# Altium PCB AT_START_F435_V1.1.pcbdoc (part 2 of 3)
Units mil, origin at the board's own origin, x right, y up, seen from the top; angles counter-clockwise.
Board outline 6521.81 x 4041.5 mil, 2 copper layers (Top Layer, Bottom Layer); 158 components, 212 nets, 714 pads, 868 vias.
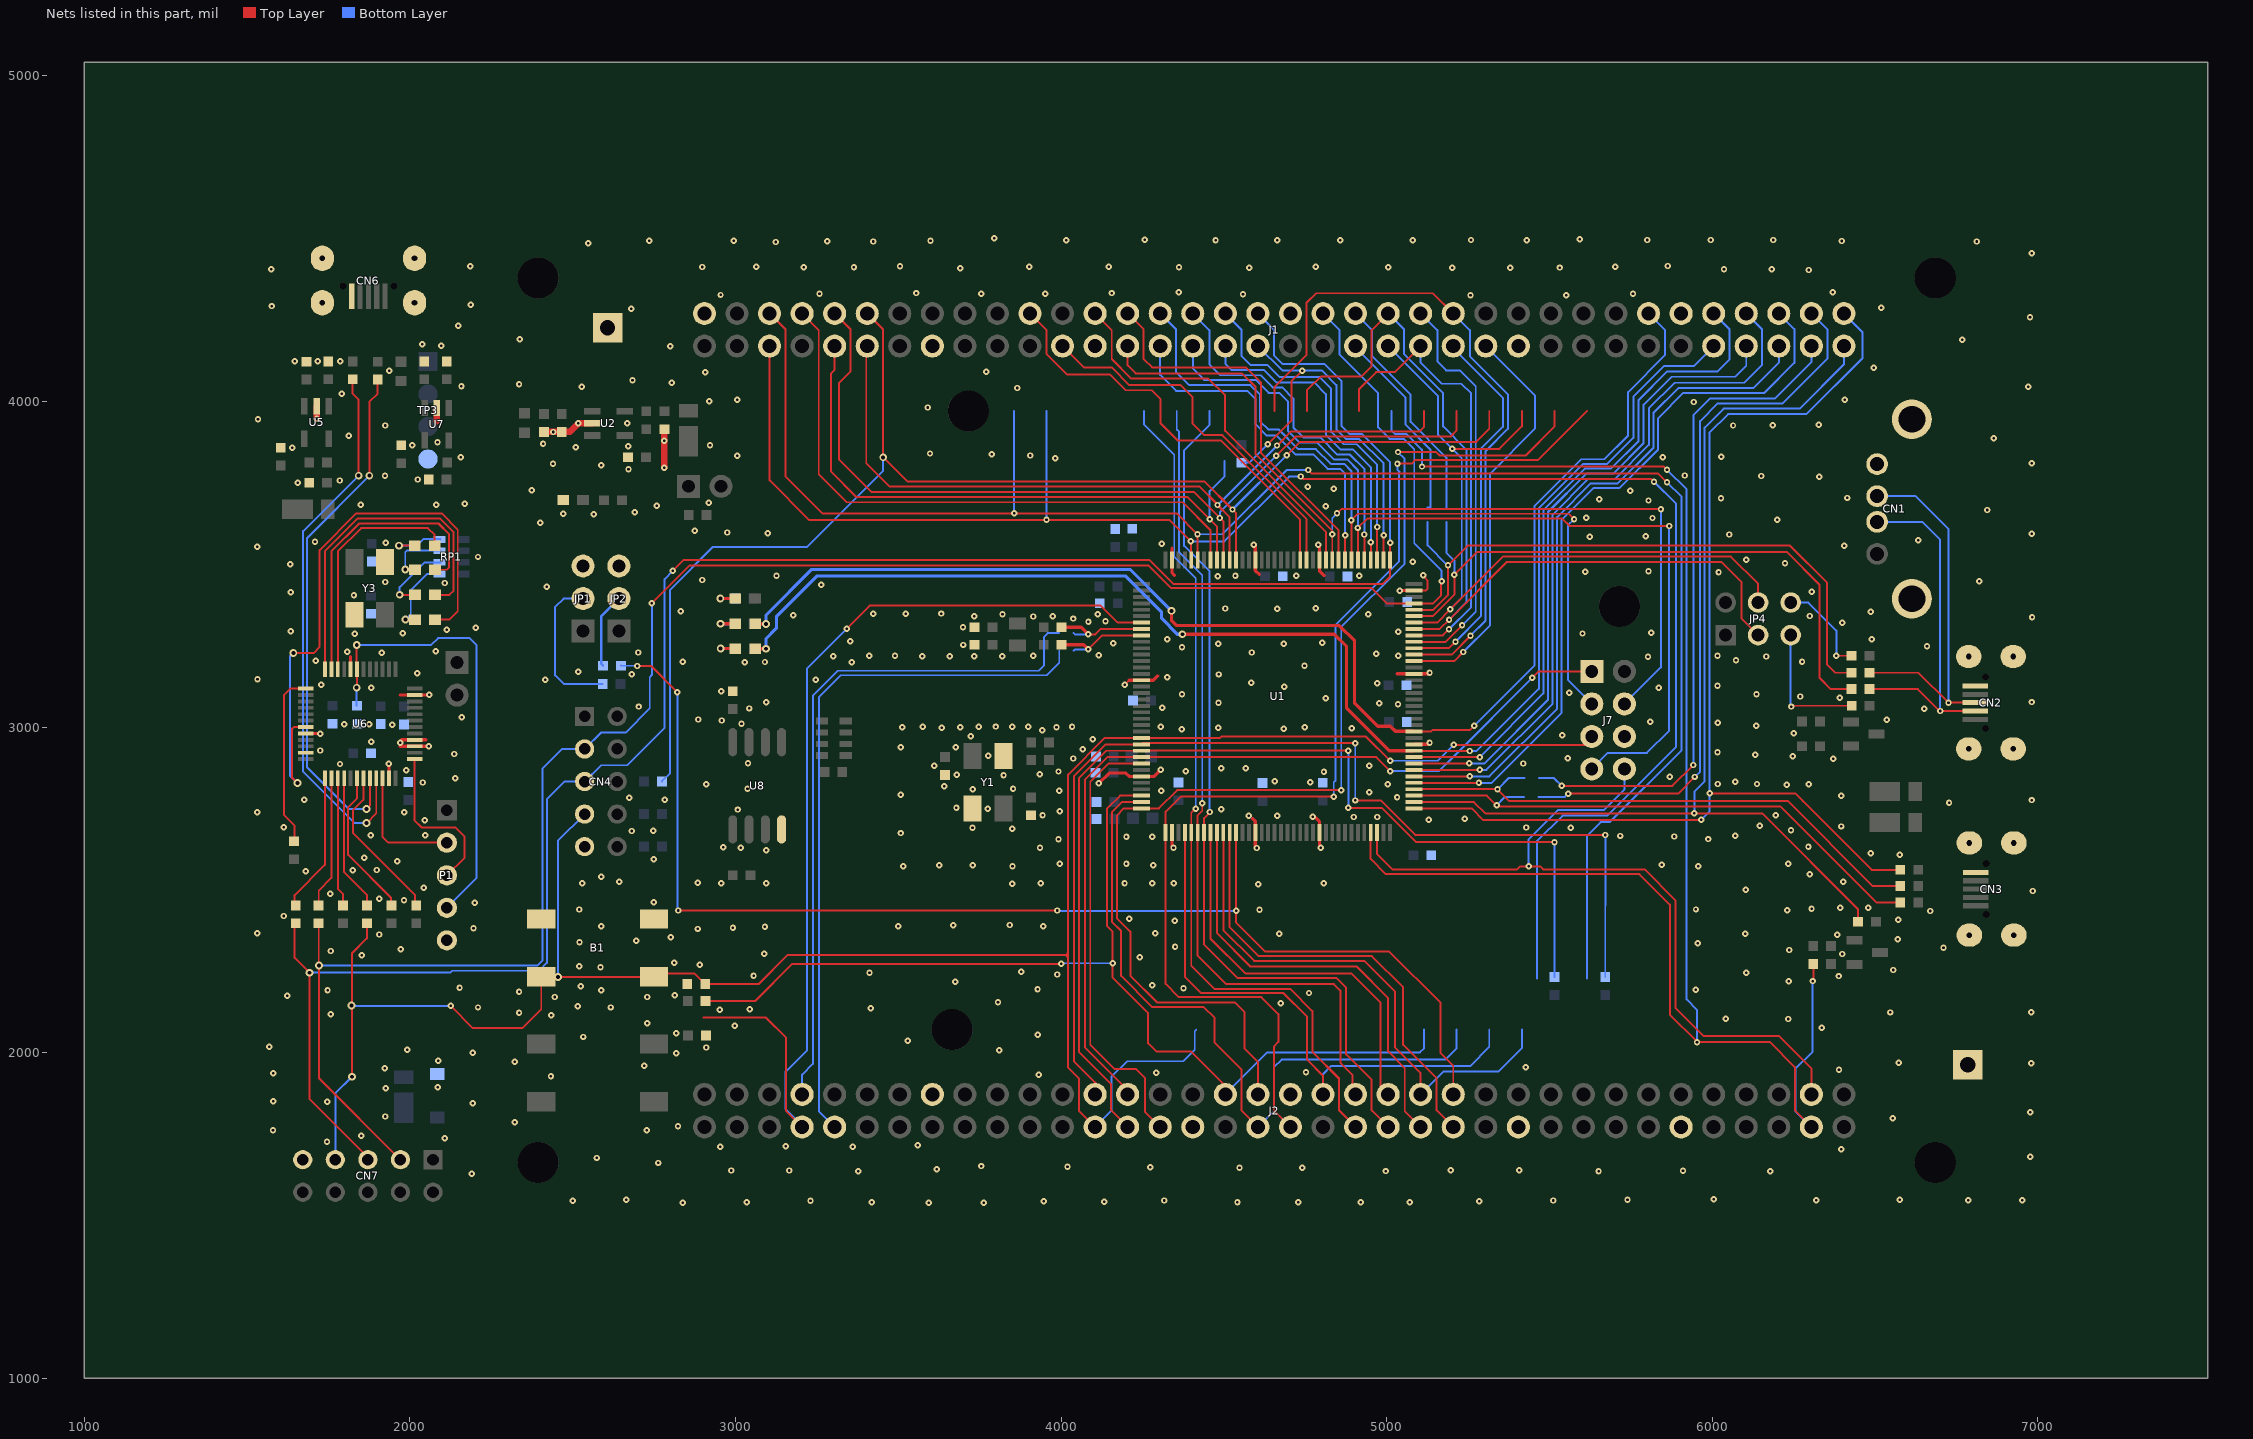
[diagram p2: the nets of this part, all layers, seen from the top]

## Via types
v1: diameter 19.69, hole 7.87, Top Layer to Bottom Layer, tented both sides, 787 vias
v2: diameter 23.62, hole 11.81, Top Layer to Bottom Layer, tented both sides, 53 vias
v3: diameter 24, hole 12, Top Layer to Bottom Layer, tented both sides, 17 vias
v4: diameter 35.43, hole 19.69, Top Layer to Bottom Layer, tented both sides, 11 vias

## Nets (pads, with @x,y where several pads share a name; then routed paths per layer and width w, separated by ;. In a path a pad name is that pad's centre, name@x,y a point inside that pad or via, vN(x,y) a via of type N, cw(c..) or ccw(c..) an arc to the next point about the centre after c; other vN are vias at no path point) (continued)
GND: B1.2 B1.4 C1.1 C2.1 C3.1 C4.1 C5.2 C6.2 C7.2 C8.2 C9.2 C10.2 C11.2 C12.2 C13.2 C14.2 C15.2 C16.2 C17.2 C18.2 C19.2 C20.2 C21.1 C22.2 C23.2 C24.2 C25.2 C26.2 C27.2 C28.2 C29.2 C30.2 C31.2 C32.2 C33.2 C34.2 C35.2 C36.2 C37.2 C38.2 C39.2 C40.2 CN1.4 CN1.SH1 CN1.SH2 CN2.5 CN2.6 CN2.7 CN2.8 CN2.9 CN3.5 CN3.6 CN3.7 CN3.8 CN3.9 CN4.9 CN6.5 CN6.6 CN6.7 CN6.8 CN6.9 CN7.9 D4.2 J1.11 J1.22 J1.35 J1.48 J1.58 J1.71 J2.16 J2.31 J2.38 J2.51 J2.61 J7.6 JP1.3 JP2.3 LED1.2 P1.5 R15.2 R18.1 R49.2 R51.2 T1.1 T2.1 TP3.4 U1.16 U1.31 U1.38 U1.51 U1.61 U1.83 U1.94 U1.107 U1.120 U1.130 U1.143 U2.2 U5.2 U6.8 U6.20 U6.23 U6.35 U6.39 U6.40 U6.47 U7.2 U8.4 Y1.2 Y1.4 Y3.2 Y3.4 | length 2089
  Top Layer w6: v1(4195.67,3129.47) 4209.79,3143.57 U1.16@4247.29,3143.57 ; U1.38@4340.89,2676.05 4340.89,2633.16 v1(4345.39,2628.68) ; U1.51@4596.79,2676.05 4596.79,2632.97 v1(4601.49,2628.3) ; U1.61@4793.64,2676.05 4793.59,2633.57 v1(4798.1,2629.09) ; U1.94@5084,3163.26 5128.19,3163.26 v1(5131.81,3166.89) ; U1.107@5084,3419.16 5120.89,3419.16 5125.49,3423.76 5125.49,3450.16 v1@5116.49,3459.26
  Top Layer w10: U6.20@1680.01,2980.16 v1@1719.39,2980.16 ; U6.8@1817.79,3177.07 1817.79,3216.57 ; U6.35@1935.92,2842.36 v1@1935.89,2881.66 ; 1969.99,3098.26 U6.47@2014.66,3098.28 v1@2059.39,3099.16 ; 1970.39,2940.76 U6.39@2014.66,2940.8 v1@2057.39,2940.76 ; v1@1975.09,2960.47 U6.40@2014.66,2960.47 2048.39,2960.47 ; v1(4116.08,2827.26) 4147.39,2858.57 4198.49,2858.57 4208.79,2848.26 4247.29,2848.26 4286.69,2848.26 v1(4306.81,2868.39) ; 4209.79,3143.57 4247.29,3143.57 4283.59,3143.57 4296.99,3156.97 ; v1@4340.79,2631.97 U1.38@4340.79,2676.07 ; 4340.79,3548.66 4340.79,3512.66 4340.79,3473.36 4348.19,3466.07 ; 4587.69,2719.26 4596.79,2710.26 U1.51@4596.79,2676.05 4596.79,2633.07 v1(4601.49,2628.3) ; v1(4592.03,3560.11) 4596.79,3555.36 U1.130@4596.79,3512.68 4596.79,3480.57 4608.59,3468.66 ; 4783.49,2720.07 4793.59,2710.07 U1.61@4793.64,2676.05 4793.59,2633.57 v1(4798.1,2629.09) ; v1(4789.43,3560.11) 4793.59,3555.97 U1.120@4793.64,3512.68 4793.59,3479.86 4808.29,3465.16 ; 5031.69,3163.26 U1.94@5084,3163.26 v1@5129.29,3163.26 ; v1(5039.88,3417.99) 5041.09,3419.16 U1.107@5084,3419.16 ; U1.83@5084,2946.72 5127.09,2946.66 v1(5131.81,2951.38)
  Top Layer w20: v1@1714.09,3946.26 U5.2@1714.09,3985.56 ; 2082.89,3938.76 U7.2@2082.86,3979.91 ; C5.2@2411.64,3906.5 C6.2@2466.64,3906.5 2490.79,3906.47 v1(2517.59,3933.36) U2.2@2559.69,3933.36 ; C7.2@2781.64,3914.85 v1(2781.64,3796.36) v1@2781.69,3796.36
  other v1: 2838.3,1539.26 3593.03,1539.26 3761.93,1538.86 4541.84,1540.04 4728.85,1540.04 4920.58,1540.04 5070.58,1540.04 3034.37,1540.83 3418.22,1540.83 4132.79,1541.62 3947.36,1542.8 5283.97,1542.8 2500.12,1545.15 3230.43,1544.77 4316.65,1545.56 5511.92,1545.56 6786.22,1546.37 6952.88,1546.37 6320.19,1546.73 2665.08,1547.52 5739.87,1548.31 6576.09,1547.52 6005.23,1549.48 2189.88,1627.44 3376.89,1634.92 5650.9,1634.92 6178.46,1635.32 4996.96,1636.11 5910.35,1636.49 2986.73,1637.67 3164.68,1637.67 5407.2,1638.08 5196.96,1638.86 3617.83,1642.01 4548.14,1646.34 4740.66,1645.94 4273.34,1648.31 4019.8,1649.1 3754.44,1651.45 2763.11,1660.9 2574.13,1676.26 6976.92,1679.55 6396.17,1702.63 2952.87,1710.9 3359.96,1710.9 3154.05,1712.88 3559.96,1714.85 1745.38,1725.63 2106.68,1736.28 1850.58,1744.15 1579.44,1761.02 2727.28,1760.9 2823.37,1773.32 2321.38,1786.49 6554.55,1797.74 1924.65,1803.65 6976.92,1816.65 2192.43,1844.02 1746.17,1848.57 1579.86,1850.02 1926.23,1890.72 2085.01,1893.88 2433.19,1927.43 3931.69,1931.7 1579.86,1936.85 4292.2,1938.01 4752.39,1939.18 6389.46,1947.07 1922.68,1951.4 5427.67,1954.99 2720.19,1958.93 6980.46,1966.77 6573.07,1968.73 2321.38,1972.33 2086.59,1975.43 2817.46,1998.29 2192.43,1999.02 3809.94,2007.35 1991.85,2008.55 2910.05,2015.62 1568.44,2017.78 3529.02,2035.71 2532.59,2047.93 3928.14,2054.24 2817.46,2058.97 6336.27,2076.7 2997.51,2082.61 2728.86,2089.64 6041.17,2103.49 6234.23,2103.09 2433.58,2114.05 1756.81,2118.07 2335.16,2121.93 6547.46,2123.18 6980.46,2123.97 2951.42,2131.86 3043.22,2132.64 3415.55,2135.8 2209.12,2138.55 2617.31,2138.55 2515.26,2142.89 4675.31,2151.45 3806.4,2155.09 2445,2170.74 2728.86,2170.74 1622.85,2174.8 2813.12,2175.99 4761.53,2182.95 2335.16,2187.28 2587.76,2191.34 1746.96,2191.74 5948.97,2192.53 3927.75,2194.49 4376.12,2197.26 2152.39,2199.22 2524.74,2203.24 4280.03,2207.36 3675.31,2217.59 6235.41,2218.93 6388.28,2235.09 3055.43,2235.86 3988.43,2239.8 6104.99,2244.93 3411.61,2245.72 3877.32,2248.09 6556.12,2253.59 2585.39,2261.47 2520.38,2264.64 2890.35,2269.36 2811.94,2275.26 4242.24,2292.8 1852.16,2298.91 3087.74,2303.24 6399.71,2302.84 1756.44,2312.01 6236.98,2315.07 1972.33,2317.82 6710.57,2321.76 4350.11,2324.68 5955.67,2335.55 2520.78,2338.7 2694.8,2343.84 6569.91,2348.55 2800.9,2354.22 6383.95,2361.95 1905.74,2362.74 4670.44,2364.7 6101.05,2365.49 1531.05,2366.68 4289.44,2366.68 2883.65,2379.68 2195.3,2381.72 2992.24,2383.34 3090.5,2386.38 2587.52,2388.07 3500.26,2388.34 3945.09,2388.34 3668.62,2391.61 3842.65,2391.89 4349.33,2405.39 6571.1,2408.45 4209.46,2410.41 1613,2419.47 6669.2,2434.84 6230.68,2437.59 2519.93,2439.47 4609.56,2439.24 5950.15,2439.57 6305.15,2441.93 6393.4,2444.3 6478.9,2444.3 2199.15,2460.01 2748.51,2461.64 1981.78,2468.32 1905.35,2471.88 1754.84,2488.03 6984.4,2496.3 6103.02,2500.24 2042.46,2506.55 4606.02,2517.2 3850.53,2519.16 2529.25,2519.57 2956.54,2520.34 3094.44,2519.95 3937.6,2519.55 4195,2520.36 4280.03,2520.36 4346.18,2520.36 4807.2,2520.36 2884.04,2521.12 2642.91,2525.07 6402.07,2525.07 2587.52,2540.03 6299.24,2548.32 1679.59,2556.97 1824.58,2560.14 1898.43,2560.78 3515.87,2571.93 3850.92,2572.74 5957.24,2572.74 3626.1,2575.86 3728.46,2575.86 4283.58,2575.86 5845.35,2576.28 3996.18,2579.8 4200.91,2579.8 6233.44,2580.22 1960.51,2587.72 2748.9,2594.01 1860.19,2599.01 6576.22,2607.8 6486.78,2611.74 3094.83,2621.2 3016.03,2629.47 3935.24,2628.68 2962.45,2631.05 6295.69,2631.84 3992.24,2654.61 5987.58,2655.88 4200.91,2662.49 4279.65,2662.49 5883.57,2663.76 5717.69,2665.32 6070.72,2666.11 1879.34,2667.3 2047.19,2668.09 3507.99,2674.3 2681.22,2680.59 2747.36,2681.38 6242.11,2683.05 3849.74,2687.39 3727.99,2690.16 5428.5,2691.34 5565.21,2690.93 1613,2692.12 6396.95,2694.49 6145.58,2697.24 2045.22,2714.18 5128.85,2715.62 5240.27,2717.59 4773.67,2724.43 4898.96,2723.64 4971.37,2723.51 4664.53,2727.18 4577.06,2727.97 3943.12,2728.76 6195.61,2729.16 1531.05,2738.22 1982.18,2738.61 3996.18,2741.22 3006.97,2746.49 4491.45,2747.51 3774.88,2749.26 3678.74,2751.61 6727.51,2766.99 2783.19,2776.26 6982.04,2775.64 1674.99,2777.01 2673.34,2782.55 5032,2784.53 6396.55,2788.66 3507.99,2792.41 4946.63,2799.28 3995,2804.2 4307.57,2803.62 3728.39,2809.14 3036.92,2810.32 3852.5,2809.93 3641.71,2817.8 6229.5,2822.53 2909.96,2823.89 5003.26,2824.28 6296.08,2823.72 6017.53,2824.89 6137.7,2824.89 2039.7,2829.62 4765.39,2830.8 6070.32,2831.59 4656.65,2832.78 2139.44,2843.01 5869.78,2847.36 3823.34,2851.7 3679.53,2853.26 3934.45,2855.24 3992.24,2863.26 4807.55,2863.11 4383.21,2863.91 1988.48,2866.66 4491.84,2873.89 4567.83,2873.89 3610.19,2881.24 4946.63,2881.24 1785.18,2886.36 1935.29,2887.16 3038.49,2888.34 5419.04,2887.93 4038.07,2903.3 6372.13,2902.51 5556.41,2904.2 6248.02,2909.61 3776.45,2911.57 6132.18,2914.34 2136.44,2917.01 6016.34,2922.22 1724.9,2927.74 4066.44,2932.07 3507.99,2938.07 3676.38,2937.97 2057.43,2940.74 1970.36,2952.16 1880.92,2955.32 4097.56,2962.8 3722.08,2971.47 5539.87,2974.68 1724.9,2979.34 6249.99,2981.32 3942.33,2990.38 4371,2993.53 4684.23,2994.72 3633.98,2997.12 4482.9,2997.07 4893.44,2996.68 3512.47,2999.05 3690.96,2999.05 4748.85,2999.05 3747.3,3000.22 3986.06,2999.84 4306.41,3000.28 3575.12,3000.62 3799.7,3001.41 3850.13,3001.01 3898.99,3000.62 4033.74,3001.01 6134.94,3003.78 1945.54,3006.53 1798.57,3008.11 1874.62,3008.11 3018.4,3010.47 6017.13,3013.24 5810.35,3016.03 2957.72,3019.93 2885.23,3023.09 6536.42,3022.68 2158.69,3030.57 6651.47,3055.78 3042.43,3056.97 4310.32,3058.93 2703.2,3062.88 5034.89,3069.57 4483.68,3073.91 4977.76,3073.51 3094.05,3076.28 6981.25,3076.66 4812.67,3088.49 6391.43,3090.07 6270.47,3093.61 2059.4,3099.12 4371.39,3100.3 6136.12,3101.09 5561.13,3104.61 2955.75,3110.16 1881.36,3121.01 5836.33,3121.14 4685.81,3123.95 6016.34,3127.09 1728.05,3129.47 4970.67,3134.97 4584.76,3136.49 2415.18,3145.22 3246.97,3144.76 1531.84,3146.8 4325.69,3153.11 4484.08,3161.38 2680.74,3161.76 2022.76,3165.7 2516.84,3170.05 4747.66,3188.16 3029.04,3198.41 3357.24,3198.41 2837.95,3199.99 3090.5,3199.59 6275.99,3200.78 1710.32,3203.53 6073.08,3204.72 5802.87,3215.24 3733.51,3217.32 6166.06,3216.53 3300.51,3217.59 3573.94,3217.72 3658.25,3217.72 3819.01,3217.72 5036.33,3218.39 3410.82,3218.51 3490.02,3218.51 3915.14,3218.51 6016.34,3218.51 4115.29,3220.47 4968.7,3225.59 1913.23,3228.36 2701.23,3228.74 4585.34,3228.74 1807.64,3231.51 2079.5,3232.3 4371.39,3244.51 6659.75,3247.66 3700.02,3251.99 4684.23,3255.14 4482.9,3256.32 4160.6,3257.51 4802.04,3258.7 3352.48,3263.26 4325.69,3269.34 6490.33,3268.93 1830.88,3286.28 5601.69,3287.28 1977.45,3288.24 5812.71,3290.03 5036.33,3292.8 1633.62,3294.01 2112.59,3298.09 2202.44,3305.01 3698.84,3306.36 6398.92,3319.76 4084.17,3323.7 4136.57,3324.89 4037.28,3333.16 6982.43,3337.49 3914.35,3339.47 3733.9,3340.26 3974.24,3340.26 6299.63,3341.03 3176.89,3343.18 3820.19,3346.16 3423.04,3347.34 3523.51,3347.34 4112.93,3346.55 4943.09,3346.55 3631.86,3348.53 6487.57,3354.43 2832.4,3354.99 4663.74,3363.49 4503.78,3363.89 4782.73,3365.07 1828.12,3404.07 1633.35,3414.01 6306.33,3415.11 2420.2,3430.2 3263.86,3436.39 2106.68,3442.3 1924.26,3445.45 6820.5,3447.82 2897.36,3451.45 4481.71,3463.18 4535.69,3463.97 4722.05,3464.36 4915.51,3463.97 3125.96,3464.76 5112.11,3465.93 6019.5,3475.39 5609.56,3477.05 5804.44,3478.22 1632.78,3500.01 6223.59,3502.97 5079.81,3508.09 6104.99,3513.22 2209.12,3522.28 1530.65,3553.41 6405.62,3556.95 4309.54,3562.47 1925.84,3566.01 1708.35,3568.78 6632.95,3573.11 5623.92,3584.53 5795.7,3585.72 6052.99,3591.22 6981.64,3593.59 3099.33,3595.16 2974.13,3597.51 2875.38,3602.66 2399.9,3626.76 6199.55,3636.14 5816.59,3642.05 5613.68,3642.84 2564.9,3653.88 2471.13,3655.05 2690.98,3659.78 6844.53,3666.49 4813.46,3678.3 2757.96,3679.88 1849.01,3682.64 2081.07,3683.03 2168.93,3685.39 2917.38,3689.36 5804.37,3695.64 5652.68,3699.97 6026.98,3703.12 6415.07,3703.51 5748.03,3725.59 2374.53,3727.43 4837.5,3731.89 4757.51,3737.41 1655.55,3750.41 1784,3757.11 2023.94,3760.26 6329.18,3768.14 6150.3,3770.89 1923.47,3771.68 5916.27,3772.47 2671.28,3791.78 2587.52,3804.61 2439.49,3808.93 6981.64,3810.3 3982.52,3824.88 2155.54,3828.03 5847.71,3828.03 6028.16,3829.99 3004.84,3833.74 3905.29,3833.93 3787.12,3837.28 3597.36,3840.03 1638.61,3857.57 2508.78,3858.93 2670.5,3862.7 2007.39,3865.05 2921.77,3865.62 2408.88,3870.18 2084.62,3874.12 2781.59,3879.7 6865.41,3887.51 1812.09,3894.57 2439.61,3906.03 1924.41,3926.01 6064.02,3926.12 6186.55,3927.32 6326.82,3928.49 2667.44,3932.55 1533.41,3945.05 1714.09,3946.22 3590.67,3981.38 5943.85,3998.24 2919.01,4000.66 6407.19,4004.93 3004.84,4005.78 1790.69,4023.05 3865.89,4041.18 2528.07,4045.16 6970.61,4045.11 2158.3,4046.7 2335.16,4052.64 2804.05,4056.97 2683.58,4065.62 2906.81,4089.24 3770.64,4091.01 1936.87,4094.36 6496.63,4103.82 1646.1,4123.12 1716.62,4123.52 1785.57,4123.91 2800.12,4169.95 2096.44,4171.19 2037.34,4175.14 6767.7,4189.72 2337.12,4191.6 2148.84,4231.88 6976.13,4258.27 2679.64,4284.12 6519.09,4288.22 1575.44,4293.02 2187.44,4297.02 5257.59,4325.85 5551.69,4325.85 2954.05,4327.05 4558.77,4329.01 3257.99,4330.98 3755.23,4330.59 3950.9,4330.59 5756.8,4331.38 3555.23,4332.94 4156.02,4332.94 4361.14,4334.91 6370.19,4334.91 6296.87,4403.65 1574.44,4406.02 6036.33,4406.18 6183.18,4406.18 3690.27,4408.53 4578.46,4410.11 5201.69,4410.51 5380.03,4410.9 5532,4411.3 3209.17,4412.48 3363.89,4412.48 4362.32,4412.48 5004.44,4411.69 2898.15,4412.86 5702.08,4413.27 3063.89,4414.05 3902.48,4413.65 4146.57,4413.65 4781.94,4414.3 2185.17,4415.02 3505.23,4415.23 5863.5,4416.02 6981.25,4455.66 2548.15,4486.1 3124.13,4489.64 3422.95,4491.22 6812.31,4491.22 3281.61,4492.4 6397.35,4492.78 2735.16,4493.57 2994.6,4493.57 3598.93,4493.97 5080.82,4494.76 5430.03,4494.76 4015.86,4495.55 4474.52,4495.55 4663.5,4495.55 4857.59,4495.55 5259.17,4495.94 5800.5,4495.94 5994.99,4495.94 6187.12,4495.94 4257.59,4497.11 5593.81,4498.69 3795.39,4501.06
JP1_2: JP1.2 R13.1 | length 463
  Bottom Layer w6: JP1.2@2531.79,3394.57 2472.19,3394.57 2446.29,3368.66 2446.29,3158.66 2472.59,3132.36 R13.1@2592.19,3132.36
JP2_2: JP2.2 R14.1 | length 231.4
  Bottom Layer w7.5: R14.1@2593.14,3188.35 2586.99,3194.57 2586.99,3339.66 JP2.2@2641.79,3394.57
LD1: LD1.2 U6.10 | length 731.2
  Top Layer w6: U6.10@1778.39,3177.07 1778.39,3539.57 1849.79,3610.97 2054.89,3610.97 2075.89,3590.07 LD1.2@2075.89,3557.07
LD1_1: LD1.1 RP1.8 | length 183.7
  Top Layer w6: v2@1966.49,3557.07 LD1.1@2014.89,3557.07
  Bottom Layer w6: v2@1966.49,3557.07 2021.49,3557.07 2041.29,3576.86 RP1.8@2093.59,3576.86
  other v2: 1966.44,3557.01
LD2: LD2.2 U6.11 | length 921.5
  Top Layer w6: U6.11@1758.79,3177.07 1758.79,3539.66 1844.19,3625.07 2087.79,3625.07 2120.09,3592.76 2120.09,3490.26 2112.79,3482.97 LD2.2@2076.79,3482.97
LD2_1: LD2.1 RP1.7 | length 193.2
  Top Layer w6: v2(1985.72,3483.66) 2014.19,3483.66 LD2.1@2015.39,3482.47
  Bottom Layer w6: v2(1985.72,3483.66) 1985.69,3536.86 1990.29,3541.47 RP1.7@2093.59,3541.47
LD3: LD3.2 U6.12 | length 1059.3
  Top Layer w6: U6.12@1739.09,3177.07 1739.09,3540.07 1839.99,3640.97 2091.79,3640.97 2133.89,3598.86 2133.89,3418.97 2120.89,3405.97 LD3.2@2076.86,3406.01
LD3_1: LD3.1 RP1.6 | length 227.6
  Top Layer w6: v2@1968.49,3405.97 LD3.1@2015.86,3406.01
  Bottom Layer w6: v2@1968.49,3405.97 1968.49,3429.36 2045.09,3505.97 RP1.6@2093.59,3505.97
  other v2: 1968.44,3406.01
LD4: LD4.2 U6.19 | length 1839.1
  Top Layer w6: v2@1641.89,3227.07 1703.89,3227.07 1722.89,3246.07 1722.89,3543.57 1835.29,3655.97 2097.09,3655.97 2146.89,3606.16 2146.89,3355.57 2121.19,3330.07 LD4.2@2076.79,3330.07 ; v2@1654.49,2828.07 1637.79,2844.76 1637.79,2993.97 1643.69,2999.86 U6.19@1679.99,2999.86
  Bottom Layer w6: v2(1641.86,3227.01) 1631.44,3216.59 1631.44,2851.01 v2(1654.44,2828.01)
LD4_1: LD4.1 RP1.5 | length 238.1
  Top Layer w6: v2(1986.51,3330.01) 1986.59,3330.07 LD4.1@2015.79,3330.07
  Bottom Layer w6: v2(1986.51,3330.01) 2002.49,3345.97 2002.49,3420.07 2052.99,3470.57 RP1.5@2093.59,3470.57
LED2_1: LED2.1 R26.2 | length 91.8
  Top Layer w10: v3(2954.57,3240.97) 2998.79,3240.97 LED2.1@2999.28,3240.48
  Bottom Layer w10: v3(2954.57,3240.97) 3000.49,3240.97 R26.2@3001.2,3240.28
LED3_1: LED3.1 R27.2 | length 89.1
  Top Layer w10: v3(2954.18,3317.01) LED3.1@2999.28,3317.21
  Bottom Layer w10: v3(2954.18,3317.01) R27.2@2998.19,3316.97
LED4_1: LED4.1 R28.2 | length 92.9
  Top Layer w10: v3@2953.39,3394.26 LED4.1@2999.29,3394.86
  Bottom Layer w10: v3@2953.39,3394.26 R28.2@3000.39,3394.66
  other v3: 2953.39,3394.22
M-ATLK_RX: R48.2 U6.31 | length 483.9
  Top Layer w6: U6.31@1857.18,2842.36 1857.19,2776.36 1824.89,2743.97 1824.89,2674.66 2015.89,2483.66 R48.2@2015.89,2450.97
M-ATLK_TX: R47.2 U6.30 | length 457.3
  Top Layer w6: U6.30@1837.49,2842.36 1837.49,2780.66 1810.09,2753.26 1810.09,2607.26 1941.89,2475.47 R47.2@1941.89,2450.97
M-NRST: C22.1 P1.4 U6.7 | length 1418.3
  Top Layer w6: v2(1836.37,3121.01) 1837.49,3122.16 1837.49,3177.07 1836.39,3178.16 v2@1836.39,3252.07
  Bottom Layer w6: v2(1836.37,3121.01) 1836.39,3065.36 C22.1@1836.69,3065.07 ; v2(1836.66,3252.01) 2065.44,3252.01 2086.44,3273.02 2183.44,3273.02 2204.44,3252.01 2204.44,2610.36 2204.44,2535.42 P1.4@2113.59,2444.57
M-SWCLK: P1.3 U6.37 | length 503.4
  Top Layer w6: U6.37@2014.69,2901.47 2014.69,2712.47 2035.59,2691.57 2138.89,2691.57 2167.89,2662.57 2167.89,2598.86 P1.3@2113.59,2544.57
M-SWDIO: P1.2 U6.34 | length 385.2
  Top Layer w6: U6.34@1916.23,2842.36 1916.19,2661.66 1933.29,2644.57 P1.2@2113.59,2644.57
M-USB_DM: R12.2 U6.32 | length 1614.8
  Top Layer w6: v2@1866.89,2748.07 1876.89,2758.07 U6.32@1876.86,2842.36 ; v2@1875.49,3772.07 1875.49,3998.57 1901.09,4024.26 R12.2@1901.09,4067.07
  Bottom Layer w6: v2(1866.86,2748.01) 1812.86,2748.01 1683.86,2877.02 1683.86,3580.44 v2(1875.44,3772.01)
M-USB_DP: R11.2 U6.33 | length 1693.4
  Top Layer w6: R11.2@1824.09,4068.07 1824.09,4023.76 1842.49,4005.47 v2@1842.49,3772.07 ; v2@1866.89,2705.07 1896.59,2734.66 U6.33@1896.59,2842.36
  Bottom Layer w6: v2(1842.44,3772.01) 1671.86,3601.44 1671.86,2863.01 1829.86,2705.01 v2(1866.86,2705.01)
M_ATLK_BOOT0: R45.2 U6.27 | length 395.7
  Top Layer w6: U6.27@1778.44,2842.36 1778.39,2503.16 1793.89,2487.76 R45.2@1793.89,2453.07
M_ATLK_NRST: R46.2 U6.28 | length 419.2
  Top Layer w6: U6.28@1798.12,2842.36 1798.09,2553.86 1867.89,2484.16 R46.2@1867.89,2452.07
M_ATLK_SWCLK: R41.2 U6.25 | length 427
  Top Layer w6: R41.2@1645.89,2453.97 1645.89,2483.47 1739.09,2576.66 U6.25@1739.07,2842.36
M_ATLK_SWDIO: R44.2 U6.26 | length 404.5
  Top Layer w6: R44.2@1719.89,2453.97 1719.89,2497.47 1758.79,2536.36 U6.26@1758.79,2842.36
M_ATLK_SWO: R52.2 U6.13 | length 539.8
  Top Layer w6: R52.2@1645.69,2646.97 1645.69,2696.76 1613.39,2729.07 1613.39,3098.97 1632.39,3117.97 U6.13@1680.01,3117.97
NRST: B1.1 B1.3 C40.1 CN4.7 CN7.7 J2.25 J7.5 R46.1 U1.25 | length 7109.1
  Top Layer w6: v2(1822.09,1925.57) 1822.09,2304.76 1868.09,2350.76 R46.1@1868.09,2397.06 ; v1(2125.64,2143.36) 2193.69,2075.36 2345.69,2075.36 2403.39,2133.16 2403.39,2232.76 B1.1@2749.91,2232.78 2760.49,2243.36 2873.69,2243.36 2907.19,2210.36 3070.69,2210.36 3159.69,2299.36 4021.69,2299.36 ; 4021.69,2291.63 4013.83,2299.36 4021.69,2307.53 ; J2.25@4104.61,1771.46 4055.69,1820.46 4055.69,1919.96 4021.69,1953.96 4021.69,2853.86 4134.19,2966.36 4247.29,2966.36 4488.79,2966.36 4492.79,2970.36 4936.69,2970.36 v1(5010.64,2896.36) ; v1(5205.64,2945.36) 5630.24,2945.36 J7.5@5630.23,2970.94
  Bottom Layer w6: CN7.7@1770.89,1670.96 1770.86,1874.34 v2(1822.09,1925.57) ; v2@1820.69,2144.36 1821.59,2143.36 1904.39,2143.36 v1(2125.64,2143.36) ; v3(2454.64,2232.36) 2454.64,2650.64 CN4.7@2536.53,2732.54 ; J2.25@4104.61,1771.46 4154.69,1821.46 4154.69,1925.37 4202.69,1973.37 4374.69,1973.37 4410.69,2009.37 4410.69,2065.76 4415.29,2070.36 ; v1(5010.64,2896.36) 5156.64,2896.36 v1(5205.64,2945.36)
  other v2: 1820.64,2144.36
OTG1_DM: CN1.2 CN2.2 R31.2 | length 1094.6
  Top Layer w6: R31.2@6483.09,3116.66 6631.49,3116.66 6699.19,3049.07 v1(6700.33,3049.09) 6807.39,3049.07 CN2.2@6807.49,3049.11
  Bottom Layer w6: CN1.2@6506.72,3630.27 6644.74,3630.27 6700.33,3574.68 v1(6700.33,3049.09)
OTG1_DP: CN1.3 CN2.3 R30.2 | length 1157.4
  Top Layer w6: R30.2@6483.09,3166.66 6633.49,3166.66 6725.99,3074.26 6726.39,3074.66 CN2.3@6807.49,3074.7
  Bottom Layer w6: CN1.3@6506.72,3709.01 6624.7,3709.01 6725.94,3607.77 v1(6725.94,3074.3)
OTG1_ID: JP4.6 R29.1 | length 299.9
  Top Layer w6: v1(6381.58,3218.89) 6427.79,3218.86 R29.1@6427.99,3218.7
  Bottom Layer w6: JP4.6@6241.19,3382.36 6295.39,3382.36 6381.58,3296.17 v1(6381.58,3218.89)
OTG1_VBUS: JP4.5 R34.1 | length 407.1
  Top Layer w6: v1(6242.5,3062.88) 6244.89,3065.26 R34.1@6428.59,3065.26
  Bottom Layer w6: JP4.5@6241.16,3282.33 6241.16,3064.22 v1(6242.5,3062.88)
PA0: J2.34 R19.2 U1.34 | length 3238.1
  Top Layer w6: R19.2@2908.14,2158.35 3060.69,2158.36 3174.69,2272.36 v1(4000.64,2272.36) ; U1.34@4247.29,2789.26 4181.29,2789.26 4140.89,2748.86 4140.89,2389.16 4158.69,2371.36 4158.69,2230.36 4267.69,2121.36 4267.69,2028.37 4292.69,2003.37 4398.69,2003.37 4504.59,1897.37 J2.34@4504.61,1871.46
  Bottom Layer w6: v1(4000.64,2272.36) 4002.64,2274.36 v1(4158.64,2274.36) ; J2.34@4504.61,1871.46 4633.59,2000.37 5101.99,2000.37 5115.29,2013.66 5115.29,2070.36
PA1: J2.35 U1.35 | length 2195.7
  Top Layer w6: U1.35@4247.29,2769.57 4186.89,2769.57 4155.89,2738.57 4155.89,2402.16 4184.69,2373.36 4184.69,2235.36 4280.19,2139.76 4438.29,2139.76 4471.69,2106.36 4471.69,2030.37 4553.69,1948.37 4553.69,1822.46 J2.35@4604.61,1771.46
  Bottom Layer w6: J2.35@4604.61,1771.46 4653.69,1820.37 4653.69,1954.37 4677.69,1978.37 5179.69,1978.37 5215.29,2013.96 5215.29,2070.36
PA2: J2.36 U1.36 | length 3594.1
  Top Layer w6: J2.36@4604.61,1871.46 4604.59,1971.37 4563.69,2012.37 4563.69,2124.36 4533.79,2154.26 4294.69,2154.26 4212.79,2236.16 4212.79,2371.26 4171.29,2412.76 4171.29,2727.86 4193.19,2749.86 4247.29,2749.86 4300.19,2749.86 4356.69,2806.36 v1(4860.64,2806.36) ; v1(5034.89,3844.57) 5151.89,3844.57 5162.59,3833.97 5426.89,3833.97 5515.19,3922.26 5515.19,3970.36
  Bottom Layer w6: v1(4860.64,2806.36) 4860.64,3307.45 5054.98,3501.79 5054.98,3824.48 v1(5034.89,3844.57)
PA3: J2.37 U1.37 | length 3580.9
  Top Layer w6: J2.37@4704.61,1771.46 4653.69,1822.46 4653.69,2018.57 4667.69,2032.57 4667.69,2118.26 4615.59,2170.36 4361.69,2170.36 4321.19,2210.76 U1.37@4321.2,2676.05 4321.19,2739.86 4367.69,2786.36 v1(4837.64,2786.36) ; v1(5033.31,3809.11) 5077.09,3809.07 5088.49,3820.57 5465.39,3820.57 5615.19,3970.36
  Bottom Layer w6: v1(4837.64,2786.36) 4837.59,2829.76 4842.59,2834.76 4842.59,3312.66 5038.39,3508.47 5038.39,3783.07 5039.59,3784.26 5033.29,3790.57 v1(5033.31,3809.11)
PA4: J2.40 U1.40 | length 1788.6
  Top Layer w6: U1.40@4380.19,2676.07 4380.19,2232.76 4429.69,2183.36 4681.69,2183.36 4755.69,2109.36 4755.69,1978.37 4804.59,1929.37 J2.40@4804.61,1871.46
  Bottom Layer w6: J2.40@4804.61,1871.46 4804.59,1933.87 4829.09,1958.37 5256.19,1958.37 5315.29,2017.46 5315.29,2070.36
PA5: J2.41 U1.41 | length 2616.3
  Top Layer w6: v1@4413.69,2749.36 4412.69,2749.36 4399.89,2736.57 U1.41@4399.94,2676.05 4399.89,2266.07 4470.69,2195.36 4703.59,2195.36 4771.69,2127.36 4771.69,2002.37 4853.69,1920.37 4853.69,1822.46 J2.41@4904.61,1771.46
  Bottom Layer w6: 4255.29,3970.36 4255.29,3928.76 4347.69,3836.36 4347.69,3523.36 4413.69,3457.36 v1@4413.69,2749.36
  other v1: 4413.64,2749.36
PA6: J2.42 U1.42 | length 2532
  Top Layer w6: v1@4433.69,2766.36 4433.69,2742.36 4419.59,2728.26 U1.42@4419.63,2676.05 4419.59,2297.36 4506.69,2210.36 4837.69,2210.36 4857.69,2190.36 4857.69,1968.37 4895.69,1930.37 4895.69,1880.46 J2.42@4904.61,1871.46
  Bottom Layer w6: 4355.29,3970.36 4355.29,3913.76 4362.69,3906.36 4362.69,3537.36 4433.69,3466.36 v1@4433.69,2766.36
  other v1: 4433.64,2766.36
PA7: J2.43 U1.43 | length 2682.7
  Top Layer w6: v1(4456.1,2739.01) 4456.09,2736.76 4439.29,2719.97 U1.43@4439.31,2676.05 4439.29,2331.76 4542.69,2228.36 4846.69,2228.36 4875.69,2199.36 4875.69,1994.37 4953.69,1916.37 4953.69,1822.46 J2.43@5004.61,1771.46
  Bottom Layer w6: 4455.29,3970.36 4455.29,3927.26 4377.69,3849.66 4377.69,3556.36 4456.09,3477.97 v1(4456.1,2739.01)
PA8: J1.28 U1.100 | length 1424.2
  Top Layer w6: 4915.19,3970.36 4915.19,4037.36 4967.89,4090.07 5024.59,4090.07 J1.28@5104.59,4170.06 ; U1.100@5084,3281.38 5172.69,3281.36 v1(5191.64,3300.36)
  Bottom Layer w6: J1.28@5104.59,4170.06 5104.59,4119.16 5169.49,4054.36 5229.69,4054.36 5259.49,4024.57 5259.49,3368.16 v1(5191.64,3300.36)
PA9: J1.29 JP4.3 U1.101 | length 2838.1
  Top Layer w6: 4755.29,3970.36 4755.29,4033.97 4797.69,4076.36 4921.69,4076.36 4953.69,4108.36 4953.69,4219.06 J1.29@5004.59,4270.06 ; U1.101@5084,3301.05 5163.19,3301.07 v1@5191.69,3329.66 ; v1(5191.7,3329.61) 5368.19,3506.16 6029.39,3506.16 6090.39,3445.07 6090.39,3333.07 JP4.3@6141.19,3282.36
  Bottom Layer w6: J1.29@5004.59,4270.06 5053.69,4220.97 5053.69,4144.86 5173.69,4024.86 5173.69,3923.26 5244.89,3852.07 5244.89,3382.86 v1@5191.69,3329.66
PA10: J1.30 JP4.4 U1.102 | length 2438.7
  Top Layer w6: U1.102@5083.99,3320.76 5154.89,3320.76 5195.99,3361.97 5357.19,3523.07 6057.69,3523.07 6141.19,3439.66 JP4.4@6141.19,3382.36 ; v1@5201.19,3854.47 5346.59,3854.47 5415.19,3923.07 5415.19,3970.36
  Bottom Layer w6: J1.30@5004.61,4170.04 5158.21,4016.43 5158.21,3897.37 v1(5201.16,3854.43) 5230.7,3824.88 5230.7,3507.7 5230.7,3396.59 v1(5196.04,3361.93)
PA11/OTG1_DM: R31.1 U1.103 | length 1976.9
  Top Layer w6: U1.103@5083.99,3340.47 5142.29,3340.47 5208.29,3406.47 5208.29,3467.86 5278.39,3538.07 5348.89,3538.07 6228.69,3538.07 6329.59,3437.16 6329.59,3150.76 6363.69,3116.66 R31.1@6428.09,3116.66
  Bottom Layer w6: 5183.79,3630.36 5183.79,3535.66 5208.29,3511.16 v1@5208.29,3467.86
  other v1: 5208.25,3467.91
PA11_E: J1.31 | length 710.9
  Bottom Layer w6: J1.31@4904.59,4270.06 4955.69,4218.97 4955.69,4138.36 5073.69,4020.36 5073.69,3937.36 5183.79,3827.26 5183.79,3674.76
PA12/OTG1_DP: R30.1 U1.104 | length 1948.7
  Top Layer w6: U1.104@5084,3360.11 5142.99,3360.07 5188.59,3405.66 5188.59,3497.47 5248.49,3557.36 6238.99,3557.36 6353.19,3443.07 6353.19,3191.66 6378.29,3166.66 R30.1@6427.99,3166.7
  Bottom Layer w6: 5125.79,3630.36 5125.79,3558.16 5186.49,3497.47 v1@5188.59,3497.47
  other v1: 5188.55,3497.45
PA12_E: J1.32 | length 599.4
  Bottom Layer w6: J1.32@4904.59,4170.06 4904.59,4165.36 5058.09,4011.86 5058.09,3928.86 5134.59,3852.36 5134.59,3674.76 5125.79,3674.76
PA13/SWDIO: CN4.3 CN7.3 J1.33 R44.1 U1.105 | length 6413.7
  Top Layer w6: R44.1@1719.89,2393.07 1719.89,2268.16 1720.69,2267.36 1720.69,1921.27 CN7.3@1970.89,1670.96 ; v1@2742.99,3380.47 2858.39,3495.86 4268.99,3495.86 4337.49,3427.36 4952.69,3427.36 5000.19,3379.76 U1.105@5084,3379.8 5142.59,3379.76 5167.69,3404.86 5167.69,3447.07 v1@5168.89,3448.16
  Bottom Layer w6: v2@1720.69,2267.36 2391.69,2267.36 2407.69,2283.36 2407.69,2873.26 2466.59,2932.36 CN4.3@2536.53,2932.54 ; CN4.3@2536.59,2932.57 2586.89,2982.86 2662.59,2982.86 2736.69,3056.97 2736.69,3153.47 2742.99,3159.76 v1@2742.99,3380.47 ; J1.33@4804.59,4270.06 4855.69,4218.97 4855.69,4143.56 4974.19,4025.07 4974.19,3920.26 5009.29,3885.16 5052.59,3885.16 5084.89,3852.86 5084.89,3564.07 5168.89,3480.16 v1@5168.89,3448.16
  other v1: 2742.99,3380.43 5168.85,3448.2
  other v2: 1720.64,2267.36
PA14/SWCLK: CN4.5 CN7.5 J1.37 R41.1 U1.109 | length 6353.4
  Top Layer w6: R41.1@1645.89,2393.07 1645.89,2291.07 1691.69,2245.36 1691.69,1857.27 1870.89,1678.07 CN7.5@1870.89,1670.96 ; v1@2807.19,3479.36 2841.19,3513.26 4271.29,3513.26 4345.19,3439.36 4988.69,3439.36 5010.09,3460.76 5010.09,3512.66 5010.59,3513.16 v1(5010.64,3566.36)
  Bottom Layer w6: v2(1691.64,2245.36) 2123.69,2245.36 2129.69,2251.36 2212.79,2251.36 ; 2194.69,2251.36 2396.69,2251.36 2420.69,2275.36 2420.69,2778.26 2474.59,2832.36 CN4.5@2536.53,2832.54 ; CN4.5@2536.59,2832.57 2587.79,2882.46 2667.39,2882.46 2782.39,2997.46 2782.39,3454.52 v1(2807.21,3479.34) ; J1.37@4604.59,4270.06 4653.69,4220.97 4653.69,4142.27 4681.59,4114.36 4809.69,4114.36 4861.69,4062.36 4861.69,3924.26 4885.79,3900.16 4923.79,3900.16 5010.59,3813.36 v1(5010.64,3566.36)
PA15: J1.38 R61.1 U1.110 | length 1285.5
  Top Layer w6: v1(4634.98,3868.61) 4707.69,3941.26 4707.69,4061.57 v1(4740.43,4094.36) ; U1.110@4990.39,3512.66 4990.59,3512.86 v1(4990.64,3588.36)
  Bottom Layer w6: R61.1@4554.69,3811.86 4578.29,3811.86 v1(4634.98,3868.61) ; J1.38@4604.59,4170.06 4680.29,4094.36 v1(4740.43,4094.36) ; v1(4740.43,4094.36) 4801.69,4094.36 4845.69,4050.36 4845.69,3913.97 4874.49,3885.16 4915.09,3885.16 4990.59,3809.66 v1(4990.64,3588.36)
PB0: J2.46 U1.46 | length 1680.5
  Top Layer w6: U1.46@4498.29,2676.07 4498.29,2375.66 4592.69,2281.36 4931.69,2281.36 5025.79,2187.26 5025.79,2015.27 5104.59,1936.46 J2.46@5104.61,1871.46
  Bottom Layer w6: J2.46@5104.61,1871.46 5175.49,1942.37 5343.69,1942.37 5415.29,2013.96 5415.29,2070.36
PB1: J2.47 U1.47 | length 1392.9
  Top Layer w6: U1.47@4518.05,2676.05 4517.99,2384.97 4606.69,2296.36 4954.69,2296.36 5050.69,2200.36 5050.69,2023.87 5153.69,1920.87 5153.69,1822.46 J2.47@5204.61,1771.46
PB2/BOOT1: J2.48 R14.2 U1.48 | length 3896.6
  Top Layer w6: v1(2698.64,3187.36) 2740.99,3187.35 v1(2821.38,3106.97) ; v1(2823.64,2436.36) v1(3988.64,2436.36) ; v1(4537.64,2435.36) 4537.59,2676.07 U1.48@4537.74,2676.05 ; v1(4537.64,2435.36) 4537.64,2399.36 4626.64,2310.35 5007.64,2310.35 5165.69,2152.31 5165.69,1998.27 5204.59,1959.36 J2.48@5204.61,1871.46
  Bottom Layer w6: R14.2@2648.19,3188.36 v1@2698.69,3187.36 ; v1(2821.38,3106.97) 2821.38,2438.62 v1(2823.64,2436.36) ; v1(3988.64,2436.36) 3989.64,2435.36 v1(4537.64,2435.36)
PB3: J1.61 R23.2 U1.133 | length 4154
  Top Layer w6: J1.61@3404.59,4270.06 3453.69,4220.97 3453.69,3828.36 3527.69,3754.36 4440.32,3754.36 v1(4526.63,3668.05) ; v1(4526.63,3668.05) 4537.69,3656.97 U1.133@4537.74,3512.68 ; v1@4693.29,3834.76 4734.69,3876.07 5275.59,3876.07 5315.19,3915.66 5315.19,3970.36
  Bottom Layer w6: R23.2@2773.99,2832.76 2798.89,2857.97 2798.89,3421.36 2930.89,3553.36 3219.69,3553.36 3453.69,3787.36 v3@3453.69,3828.57 ; v1(4526.63,3668.05) v1(4693.29,3834.72) v1@4693.29,3835.12
  other v3: 3453.64,3828.36
PB4: J1.62 U1.134 | length 2461.2
  Top Layer w6: J1.62@3404.59,4170.06 3401.69,4167.06 3401.69,3810.36 3473.69,3738.36 4425.63,3738.36 4480.53,3683.47 v1(4480.53,3681.84) ; v1@4480.49,3681.86 4517.99,3644.36 U1.134@4518.05,3512.68 ; v1@4663.39,3864.66 4705.89,3907.26 5099.89,3907.26 5115.19,3922.57 5115.19,3970.36
  Bottom Layer w6: v1(4480.53,3681.84) v1(4663.35,3864.66) v1@4663.35,3865.06
PB5: J1.63 U1.135 | length 2769.9
  Top Layer w6: J1.63@3304.59,4270.06 3353.69,4220.97 3353.69,4092.36 3317.69,4056.36 3317.69,3822.36 3417.69,3722.36 4407.69,3722.36 v1(4488.02,3642.05) 4498.29,3631.76 U1.135@4498.29,3512.66 ; v1(4660.98,3832.76) 4720.49,3892.26 5196.39,3892.26 5215.19,3911.07 5215.19,3970.36
  Bottom Layer w6: v1(4488.02,3642.05) 4488.01,3659.79 v1(4660.98,3832.76)
PB6: J1.64 U1.136 | length 1946
  Top Layer w6: J1.64@3304.59,4170.06 3304.59,4097.36 3293.69,4086.37 3293.69,3784.36 3371.69,3706.37 4388.63,3706.37 v1(4456.64,3638.36) ; v1(4456.64,3638.36) 4478.59,3616.36 U1.136@4478.59,3512.66
  Bottom Layer w6: v1(4456.64,3638.36) 4456.59,3724.36 4501.59,3769.36 4501.59,3817.26
PB7: J1.65 U1.137 | length 1881.5
  Top Layer w6: J1.65@3204.59,4270.06 3255.69,4218.97 3255.69,3776.26 3341.69,3690.36 4373.69,3690.36 4458.99,3604.97 U1.137@4459,3512.68
PB8: J1.67 U1.139 | length 5471.9
  Top Layer w6: J1.67@3104.59,4269.56 3153.69,4220.97 3153.69,3769.16 3266.49,3656.36 4354.69,3656.36 v1(4419.01,3592.01) 4418.99,3513.16 U1.139@4419.59,3512.57 ; v1@4759.69,3789.36 4770.59,3778.36 5834.29,3778.36 v1(5861.11,3751.59)
  Bottom Layer w6: 3855.29,3970.36 3855.29,3898.76 3855.59,3898.47 v1(3855.64,3656.36) ; v1(4419.01,3592.01) 4495.33,3592.01 4692.69,3789.36 v1@4759.69,3789.36 ; 5615.69,2227.47 5615.69,2666.36 5657.19,2707.86 5684.59,2707.86 5905.99,2929.26 5905.99,3706.66 v1(5861.11,3751.59)
  other v1: 4759.64,3789.36
PB9: J1.68 U1.140 | length 5499.2
  Top Layer w6: J1.68@3104.59,4169.56 3104.59,3757.36 3225.69,3636.36 4332.59,3636.36 4398.69,3570.36 4398.69,3513.76 U1.140@4399.89,3512.57 ; v1(4736.64,3769.36) 4743.77,3762.23 5812.64,3762.23 v1(5821.31,3753.55)
  Bottom Layer w6: v1@3955.29,3636.36 3955.29,3970.36 ; v1(4398.64,3570.36) 4501.64,3570.36 4700.64,3769.36 v1(4736.64,3769.36) ; 5461.69,2227.47 5461.69,2649.36 5540.29,2727.97 5677.49,2727.97 5889.09,2939.57 5889.09,3685.76 v1(5821.31,3753.55)
  other v1: 3955.24,3636.36
PB10: J2.69 R37.1 U1.69 | length 5378.1
  Top Layer w6: U1.69@4951.12,2676.05 4951.09,2594.86 4997.69,2548.36 5776.39,2548.36 5870.19,2454.57 5870.19,2116.86 5954.09,2032.96 6176.09,2032.96 6253.69,1955.27 6253.69,1822.46 J2.69@6304.61,1771.46 ; v1(5108.57,3800.05) 5851.65,3800.05 v1(5861.11,3790.59) ; v1@6308.29,2219.76 6310.49,2221.97 R37.1@6310.53,2272.08
  Bottom Layer w6: 5015.19,3970.36 5015.19,3909.97 5024.99,3900.16 5060.49,3900.16 5108.59,3852.07 v1@5108.59,3800.07 ; v1(5861.11,3790.59) 5921.39,3730.32 5921.39,2163.13 5953.26,2131.26 v1@5953.69,2032.16 ; J2.69@6304.61,1771.46 6255.59,1820.46 6255.59,1949.96 6308.29,2001.87 v1@6308.29,2219.76
  other v1: 5953.26,2032.16 6308.3,2219.72
PB11: J2.70 J7.8 U1.70 | length 2458.7
  Top Layer w6: U1.70@4970.81,2676.05 4970.79,2609.16 5018.19,2561.66 5395.29,2561.66 5400.19,2561.66 5410.39,2571.97 v1@5436.29,2571.97 ; v1(5436.33,2571.93) 5471.19,2571.93 5480.76,2562.36 ; 5480.79,2562.36 5792.29,2562.36 5887.09,2467.57 5887.09,2137.26 5973.69,2050.66 6205.59,2050.66 6304.59,1951.66 J2.70@6304.61,1871.46
  Bottom Layer w6: v1@5436.29,2571.97 5436.29,2654.66 5526.99,2745.26 5668.09,2745.26 5730.29,2807.47 J7.8@5730.29,2870.97
PB12/OTG2_ID: J1.1 R38.1 U1.73 | length 3505.9
  Top Layer w6: U1.73@5084,2749.88 5261.09,2749.86 5296.79,2714.16 5965.89,2714.16 v1(5966.31,2714.57) ; v1@5991.89,2796.16 6255.09,2796.16 6279.49,2771.66 6489.89,2561.26 R38.1@6577.89,2561.26
  Bottom Layer w6: v1(5966.31,2714.57) 5991.49,2739.76 5991.49,3903.57 6048.69,3960.76 6289.39,3960.76 6461.69,4133.06 6461.69,4212.97 J1.1@6404.59,4270.06
  other v1: 5991.92,2796.14
PB13/OTG2_VBUS: J1.2 R35.1 U1.74 | length 3301.7
  Top Layer w6: U1.74@5084,2769.57 5267.99,2769.57 5302.89,2734.66 v1(5945.03,2734.68) 6153.49,2734.66 6447.89,2440.26 R35.1@6447.89,2401.76
  Bottom Layer w6: v1(5945.03,2734.68) 5944.99,2801.26 5976.59,2832.76 5976.59,3919.47 6034.89,3977.76 6268.89,3977.76 6404.59,4113.47 J1.2@6404.59,4170.06
PB14/OTG2_DM: R40.1 U1.75 | length 1724.3
  Top Layer w6: U1.75@5083.99,2789.26 5307.69,2789.26 5341.59,2755.36 6210.39,2755.36 6504.39,2461.36 R40.1@6577.79,2461.36
  Bottom Layer w6: v1(5337.64,2759.36) 5363.59,2785.36 5421.49,2785.36
PB14_E: J1.3 | length 2235.9
  Top Layer w6: v1(5557.64,2795.36) 5895.79,2795.36 v1(5947,2846.57)
  Bottom Layer w6: 5465.89,2785.36 5547.59,2785.36 v1(5557.64,2795.36) ; v1(5947,2846.57) 5963.19,2862.76 5963.19,3939.57 6017.49,3993.86 6216.09,3993.86 6354.69,4132.47 6354.69,4219.97 J1.3@6304.59,4270.06
PB15/OTG2_DP: R39.1 U1.76 | length 1714
  Top Layer w6: U1.76@5083.99,2808.97 5340.09,2808.97 5375.69,2773.36 6231.39,2773.36 6493.39,2511.36 R39.1@6577.79,2511.36
  Bottom Layer w6: v1@5340.69,2809.36 5374.69,2843.36 5423.49,2843.36
  other v1: 5340.64,2809.36
PB15_E: J1.4 | length 2064.2
  Top Layer w6: v1@5537.69,2819.36 5878.03,2819.36 v1(5941.88,2883.22)
  Bottom Layer w6: 5467.89,2843.36 5513.69,2843.36 v1@5537.69,2819.36 ; v1@5942.29,2883.16 5942.29,3957.66 5993.89,4009.26 6193.29,4009.26 6304.59,4120.56 J1.4@6304.59,4170.06
  other v1: 5537.64,2819.36
PC0: J2.26 R59.1 U1.26 | length 3335.7
  Top Layer w6: J2.26@4104.61,1871.46 4105.69,1872.46 4105.69,1907.37 4039.69,1973.37 4039.69,2849.36 4136.99,2946.66 4247.29,2946.66 4250.79,2950.16 v1(4903.69,2950.2) ; v1@4903.69,2774.36 4981.39,2774.36 5087.39,2668.36 v1@5671.69,2668.36
  Bottom Layer w6: v1(4903.64,2774.36) 4903.64,2950.15 v1(4903.69,2950.2) ; R59.1@5671.64,2231.85 v1@5671.69,2668.36
  other v1: 5671.64,2668.36
PC1: J2.27 R57.1 U1.27 | length 3262.4
  Top Layer w6: J2.27@4204.61,1771.46 4153.69,1822.46 4153.69,1903.37 4055.79,2001.27 4055.79,2843.76 4139.09,2927.07 4247.29,2927.07 4247.69,2927.36 v1(4882.64,2927.36) ; v1(4882.64,2751.36) 4985.49,2751.36 5090.49,2646.36 v1@5515.69,2646.36
  Bottom Layer w6: v1(4882.64,2751.36) v1@4882.64,2927.35 ; R57.1@5515.64,2231.85 v1@5515.69,2646.36
  other v1: 5515.64,2646.36
PC2: J2.28 J7.1 U1.28 | length 2751.9
  Top Layer w6: J2.28@4204.61,1871.46 4204.59,1884.37 4073.09,2015.87 4073.09,2838.26 4142.19,2907.36 4247.29,2907.36 4931.69,2907.36 4968.69,2907.36 v1(5011.64,2864.36) ; v1@5447.69,3151.36 5467.19,3170.97 J7.1@5630.29,3170.97
  Bottom Layer w6: v1(5011.64,2864.36) 5160.64,2864.36 5202.64,2906.36 v1(5447.64,3151.36)
PC3: J2.29 U1.29 | length 1369.1
  Top Layer w6: U1.29@4247.29,2887.66 4144.99,2887.66 4089.69,2832.36 4089.69,2024.27 4164.59,1949.37 4230.69,1949.37 4257.69,1922.27 4257.69,1818.46 J2.29@4304.61,1771.46
PC4: J2.44 U1.44 | length 1220.9
  Top Layer w6: U1.44@4459,2676.05 4458.99,2350.07 4565.69,2243.36 4890.69,2243.36 4981.69,2152.36 4981.69,1894.46 J2.44@5004.61,1871.46
PC5: J2.45 U1.45 | length 1354.9
  Top Layer w6: U1.45@4478.59,2676.07 4478.59,2367.36 4581.69,2264.36 4907.69,2264.36 5004.59,2167.47 5004.59,2003.46 5055.69,1952.37 5055.69,1820.46 J2.45@5104.61,1771.46
PC6: J1.24 U1.96 | length 1256.6
  Top Layer w6: U1.96@5083.99,3202.66 5207.89,3202.66 v1(5235.64,3230.36)
  Bottom Layer w6: v1(5235.64,3230.36) 5317.69,3312.36 5317.69,3778.36 5455.69,3916.36 5455.69,4018.97 J1.24@5304.59,4170.06
PC7: J1.25 U1.97 | length 2166.5
  Top Layer w6: 4655.29,3970.36 4655.29,4043.97 4753.69,4142.36 4753.69,4302.36 4783.69,4332.36 5142.29,4332.36 J1.25@5204.59,4270.06 ; U1.97@5084,3222.32 5199.59,3222.26 v1(5257.64,3280.36)
  Bottom Layer w6: J1.25@5204.59,4270.06 5255.69,4218.97 5255.69,4138.36 5372.59,4021.47 5372.59,3915.97 5303.69,3847.07 5303.69,3326.36 v1(5257.64,3280.36)
PC8: J1.26 U1.98 | length 1167
  Top Layer w6: U1.98@5084,3242.01 5191.29,3241.97 v1(5211.64,3262.36)
  Bottom Layer w6: J1.26@5204.59,4170.06 5204.59,4163.36 5356.79,4011.16 5356.79,3921.76 5289.69,3854.66 5289.69,3340.36 v1(5211.64,3262.36)
PC9: J1.27 U1.99 | length 1238.1
  Top Layer w6: U1.99@5084,3261.68 5180.99,3261.66 v1(5231.64,3312.36)
  Bottom Layer w6: J1.27@5104.59,4270.06 5155.69,4218.97 5155.69,4122.86 5182.99,4095.57 5224.39,4095.57 5273.69,4046.26 5273.69,3354.36 v1(5231.64,3312.36)
PC10: J1.39 U1.111 | length 1076.1
  Top Layer w6: v1(4970.64,3614.36) 4970.59,3512.76 U1.111@4970.81,3512.68
  Bottom Layer w6: J1.39@4504.59,4270.06 4553.69,4220.97 4553.69,4140.36 4581.69,4112.36 4633.69,4112.36 4670.69,4075.36 4792.69,4075.36 4829.69,4038.36 4829.69,3906.76 4867.79,3868.57 4908.09,3868.57 4970.59,3806.07 v1(4970.64,3614.36)
PC11: J1.40 U1.112 | length 991
  Top Layer w6: U1.112@4951.12,3512.68 4951.59,3513.26 v1(4951.64,3567.36)
  Bottom Layer w6: J1.40@4504.59,4170.06 4504.59,4116.36 4524.59,4096.36 4623.59,4096.36 4661.59,4058.36 4777.59,4058.36 4813.59,4022.36 4813.59,3897.26 4858.79,3852.07 4896.89,3852.07 4951.59,3797.36 v1(4951.64,3567.36)
PC12: J1.41 U1.113 | length 1117.9
  Top Layer w6: U1.113@4931.44,3512.68 4931.59,3512.97 v1(4931.64,3591.36)
  Bottom Layer w6: J1.41@4404.59,4270.06 4455.69,4218.97 4455.69,4114.27 4489.69,4080.36 4612.69,4080.36 4649.69,4043.36 4678.69,4043.36 4713.69,4008.36 4713.69,3919.97 4744.29,3889.36 4795.49,3889.36 4848.09,3836.66 4887.49,3836.66 4931.59,3792.57 v1(4931.64,3591.36)
PC13: J2.7 U1.7 | length 3159.8
  Top Layer w6: 2901.89,2107.36 3093.69,2107.36 3154.69,2046.37 3154.69,1821.46 J2.7@3204.61,1771.46 ; v1(3341.64,3302.36) 3412.19,3372.97 4121.59,3372.97 4173.79,3320.76 U1.7@4247.29,3320.76
  Bottom Layer w6: J2.7@3204.59,1771.57 3204.59,1775.37 3153.69,1826.57 3153.69,1941.27 3219.69,2007.27 3219.69,3180.36 v1(3341.64,3302.36)
PC14/LEXT_IN: R5.2 U1.8 | length 308
  Top Layer w6: v1@4083.69,3284.36 4105.59,3284.36 4122.29,3301.07 U1.8@4247.29,3301.07
  Top Layer w10: R5.2@4001.79,3306.57 4061.39,3306.57 v1@4083.69,3284.36
  Bottom Layer w6: 4038.89,3288.36 4042.89,3284.36 v1@4083.69,3284.36
  other v1: 4083.64,3284.36
PC14_E: J2.8 | length 2125.9
  Bottom Layer w6: J2.8@3204.59,1871.57 3204.59,1931.96 3237.69,1965.07 3237.69,3095.76 3314.59,3172.76 3931.19,3172.76 3947.89,3189.36 3947.89,3277.16 3958.99,3288.36 3994.49,3288.36
PC15/LEXT_OUT: R6.2 U1.9 | length 315.8
  Top Layer w6: v1@4083.69,3238.36 4126.69,3281.36 U1.9@4247.29,3281.36
  Top Layer w10: R6.2@4001.74,3252.78 4069.19,3252.76 v1@4083.69,3238.36
  Bottom Layer w6: 4038.89,3234.36 4042.89,3238.36 v1@4083.69,3238.36
  other v1: 4083.64,3238.36
PC15_E: J2.9 | length 2159.3
  Bottom Layer w6: J2.9@3304.61,1771.46 3255.99,1820.07 3255.99,3091.26 3323.79,3158.97 3956.09,3158.97 3994.49,3197.47 3994.49,3234.36
PD0: J1.42 J7.7 U1.114 | length 2926.1
  Top Layer w6: v1(4911.64,3611.36) 4911.59,3512.76 U1.114@4911.75,3512.68 ; v1@4911.69,3611.57 4940.69,3640.36 5539.29,3640.36 5562.29,3617.36 v1(5867.64,3617.36)
  Bottom Layer w6: J1.42@4404.59,4170.06 4404.59,4101.36 4439.69,4066.36 4597.69,4066.36 4637.59,4026.36 4669.69,4026.36 4697.69,3998.36 4697.69,3908.97 4733.29,3873.36 4786.99,3873.36 4838.29,3822.07 4878.89,3822.07 4911.59,3789.36 v1(4911.64,3611.36) ; J7.7@5630.29,2870.97 5679.69,2920.36 5799.39,2920.36 5867.59,2988.66 v1(5867.64,3617.36)
PD1: J1.43 J7.3 U1.115 | length 2490.6
  Top Layer w6: v1(4891.64,3635.36) 4891.59,3513.07 U1.115@4891.99,3512.66 ; v1(4891.64,3635.36) 4911.34,3655.06 5558.94,3655.06 v1(5575.64,3638.36)
  Bottom Layer w6: J1.43@4304.59,4270.06 4353.69,4220.97 4353.69,4090.26 4393.69,4050.36 4581.69,4050.36 4611.69,4020.36 4611.69,3938.26 4635.89,3914.07 4667.89,3914.07 4728.69,3853.36 4782.99,3853.36 4828.39,3807.97 4870.09,3807.97 4891.59,3786.36 v1(4891.64,3635.36) ; v1(5575.64,3638.36) 5556.69,3619.36 5556.69,3144.57 J7.3@5630.29,3070.97
PD2: J1.44 U1.116 | length 1092.9
  Top Layer w6: U1.116@4872.29,3512.66 4872.59,3512.97 v1(4872.64,3588.36)
  Bottom Layer w6: J1.44@4304.59,4170.06 4304.59,4081.36 4353.69,4032.36 4571.69,4032.36 4597.69,4006.36 4597.69,3929.36 4632.19,3894.86 4662.19,3894.86 4719.69,3837.36 4774.19,3837.36 4818.99,3792.57 4857.99,3792.57 4872.59,3777.97 v1(4872.64,3588.36)
PD3: J1.45 U1.117 | length 1194.6
  Top Layer w6: J1.45@4204.61,4270.04 4253.64,4221 4253.64,4146.35 ; 4253.69,4146.36 4253.69,4130.16 4279.49,4104.36 4567.59,4104.36 4613.69,4058.36 4613.69,3842.97 4852.69,3603.97 U1.117@4852.7,3512.68
PD4: J1.46 J7.4 U1.118 | length 2824.8
  Top Layer w6: J1.46@4204.59,4170.06 4204.59,4111.06 4229.29,4086.36 4555.69,4086.36 4597.69,4044.36 4597.69,3838.36 4832.99,3602.97 4832.99,3591.86 U1.118@4833.01,3512.68 ; v1(4847.64,3656.36) 4860.64,3669.35 v1(5842.64,3669.36)
  Bottom Layer w6: v1(4832.99,3591.84) 4832.99,3641.71 v1(4847.64,3656.36) ; J7.4@5730.29,3070.97 5842.64,3183.31 v1(5842.64,3669.36)
PD5: J1.47 U1.119 | length 1189.2
  Top Layer w6: J1.47@4104.59,4270.06 4155.69,4218.97 4155.69,4130.36 4215.69,4070.36 4451.69,4070.36 4503.69,4018.36 4503.69,3909.36 4813.29,3599.66 U1.119@4813.33,3512.68
PD6: J1.50 U1.122 | length 1167.3
  Top Layer w6: J1.50@4021.64,4153 J1.50@4004.61,4170.04 4070.09,4104.56 4155.49,4104.56 4209.69,4050.36 4367.69,4050.36 4403.69,4014.26 4403.69,3932.36 4439.69,3896.36 4495.69,3896.36 4754.19,3637.76 U1.122@4754.19,3512.66
PD7: J1.51 U1.123 | length 1303.2
  Top Layer w6: J1.51@3904.59,4270.06 3955.69,4218.97 3955.69,4144.97 4017.69,4082.97 4149.99,4082.97 4198.59,4034.36 4278.09,4034.36 4305.69,4006.76 4305.69,3932.26 4357.69,3880.36 4490.69,3880.36 4734.59,3636.36 U1.123@4734.59,3512.68
PD8: J1.5 U1.77 | length 2278.2
  Top Layer w6: U1.77@5084,2828.61 v1@5283.69,2828.57
  Bottom Layer w6: v1@5283.69,2828.57 5322.89,2828.57 5537.69,3043.36 5537.69,3636.36 5635.69,3734.36 5715.69,3734.36 5833.69,3852.36 5833.69,3948.36 5911.69,4026.36 6084.13,4026.36 ; 6084.09,4026.36 6160.69,4026.36 6252.69,4118.36 6252.69,4221.97 J1.5@6204.59,4270.06
  other v1: 5283.64,2828.61
PD9: J1.6 U1.78 | length 2104.9
  Top Layer w6: U1.78@5084,2848.3 v1@5255.69,2848.26
  Bottom Layer w6: v1@5255.69,2848.26 5315.59,2848.26 5523.69,3056.36 5523.69,3644.36 5627.69,3748.36 5709.69,3748.36 5819.69,3858.36 5819.69,3965.07 5896.59,4041.97 6127.49,4041.97 6204.59,4119.06 J1.6@6204.59,4170.06
  other v1: 5255.64,2848.3
PD10: J1.7 U1.79 | length 2169.6
  Top Layer w6: U1.79@5084,2867.99 5084.29,2868.36 v1@5285.69,2868.36
  Bottom Layer w6: v1@5285.69,2868.36 5306.69,2868.36 5509.69,3071.36 5509.69,3652.36 5619.69,3762.36 5701.69,3762.36 5805.69,3866.36 5805.69,3978.66 5884.39,4057.36 6099.09,4057.36 6153.69,4111.97 6153.69,4220.97 J1.7@6104.59,4270.06
  other v1: 5285.64,2868.36
PD11: J1.8 U1.80 | length 1994.4
  Top Layer w6: U1.80@5084,2887.68 5084.69,2888.36 v1@5253.69,2888.36
  Bottom Layer w6: v1@5253.69,2888.36 5300.69,2888.36 5495.69,3083.36 5495.69,3660.36 5613.69,3778.36 5695.69,3778.36 5789.69,3872.36 5789.69,3990.26 5875.29,4075.86 6071.09,4075.86 6104.59,4109.36 J1.8@6104.59,4170.06
  other v1: 5253.64,2888.36
PD12: J1.9 U1.81 | length 2039.9
  Top Layer w6: U1.81@5084,2907.36 v1@5285.69,2907.36
  Bottom Layer w6: v1@5285.69,2907.36 5481.69,3103.36 5481.69,3666.36 5609.69,3794.36 5689.69,3794.36 5773.69,3878.36 5773.69,4003.36 5862.69,4092.36 6016.69,4092.36 6053.69,4129.36 6053.69,4220.97 J1.9@6004.59,4270.06
  other v1: 5285.64,2907.34
PD13: J1.10 LED2.2 U1.82 | length 4334.9
  Top Layer w6: U1.82@5083.99,2927.07 5084.59,2926.36 v1(5255.64,2926.36)
  Top Layer w10: LED2.2@3060.28,3240.48 v3@3093.69,3240.47 ; v2(4372.58,3285.09) 4839.09,3285.07 4876.89,3247.26 4876.89,3058.07 5007.89,2927.07 U1.82@5083.99,2927.07
  Bottom Layer w6: v1(5255.64,2926.36) 5276.69,2926.36 5467.69,3117.36 5467.69,3672.36 5603.69,3808.36 5677.69,3808.36 5757.69,3888.36 5757.69,4014.36 5851.69,4108.36 5942.89,4108.36 J1.10@6004.59,4170.06
  Bottom Layer w10: v3@3093.69,3240.47 3093.69,3271.66 3125.59,3303.57 3125.59,3339.07 3250.49,3463.97 4197.59,3463.97 4308.79,3352.86 4308.79,3333.47 4357.19,3285.07 v2(4372.58,3285.09)
  other v3: 3093.65,3240.47
PD14: J1.13 LED3.2 U1.85 | length 5175
  Top Layer w6: U1.85@5084,2986.09 5135.79,2986.07 5140.09,2990.36 5255.69,2990.36 v1@5269.69,3004.36
  Top Layer w10: LED3.2@3060.28,3317.21 v3@3093.69,3316.66 ; v3(4339.09,3356.8) 4339.09,3327.66 4355.29,3311.47 4854.39,3311.47 ; 4363.89,3311.47 4854.39,3311.47 ; U1.85@5084,2986.09 5027.79,2986.07 5011.29,3002.57 ; U1.85@5083.99,2986.57 5027.79,2986.57 5011.29,3002.57 ; 4854.39,3311.47 4901.69,3264.16 4901.69,3073.16 4972.29,3002.57 ; 4854.39,3311.47 4901.69,3264.57 4901.69,3073.57 4972.29,3002.57 ; 4972.29,3002.57 5011.29,3002.57 ; 4972.29,3002.57 5011.29,3002.57
  Bottom Layer w6: v1@5269.69,3004.36 5453.69,3188.36 5453.69,3678.36 5597.69,3822.36 5668.69,3822.36 5741.69,3895.36 5741.69,4028.86 5855.69,4142.97 5855.69,4218.97 J1.13@5804.59,4270.06
  Bottom Layer w10: v3@3093.69,3316.66 3093.69,3343.76 3233.89,3484.07 4211.79,3484.07 v3(4339.09,3356.8)
  other v1: 5269.64,3004.36
  other v3: 3093.65,3316.66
